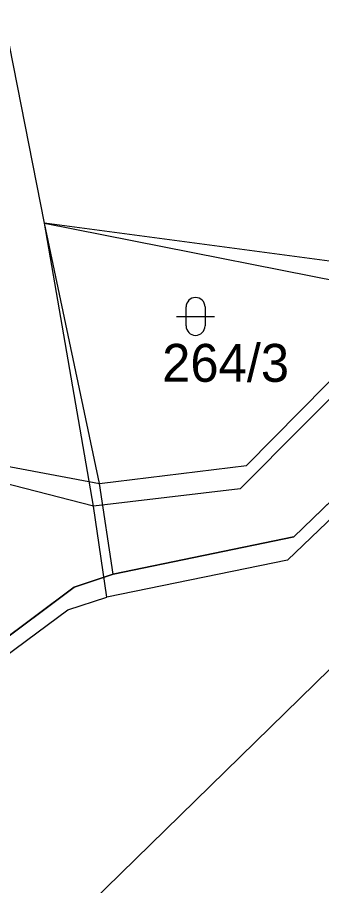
# Model space of a CAD drawing. Extents: x -678683 to -677755, y -1006946 to -1005971.
# Drawn here: x -678311.95 to -678295.9, y -1006533.89 to -1006488.07 of the extents above; entities that cross this region are included whole.
import ezdxf

# ---------------------------------------------------------------- set-up
doc = ezdxf.new("R2010")
doc.units = 0
for name, color, linetype in [('I_2_4_předběžný_vykres - SŽDC', 7, 'Continuous'), ('koor - SSZT_nové', 7, 'Continuous'), ('MapaKN - Mladejov+Strelec_dosavani+nova_situace - Vrstva 1', 7, 'Continuous'), ('MapaKN - Mladejov+Strelec_dosavani+nova_situace - Vrstva 11', 7, 'Continuous'), ('MapaKN - Mladejov+Strelec_dosavani+nova_situace - Vrstva 18', 7, 'Continuous'), ('MapaKN - Mladejov+Strelec_dosavani+nova_situace - Vrstva 25', 7, 'Continuous'), ('MapaKN - původní vrstava 1', 7, 'Continuous')]:
    doc.layers.add(name, color=color, linetype=linetype)

msp = doc.modelspace()

# ---------------------------------------------------------------- linework, layer by layer
at = {"layer": 'I_2_4_předběžný_vykres - SŽDC'}
for p, q in [((-678286.495, -1006504.981), (-678297.37, -1006515.48)), ((-678297.37, -1006515.48), (-678306.89, -1006517.45)), ((-678306.89, -1006517.45), (-678308.95, -1006518.13)), ((-678308.95, -1006518.13), (-678313.38, -1006521.44))]:
    msp.add_line(p, q, dxfattribs=at)
at = {"layer": 'koor - SSZT_nové'}
msp.add_lwpolyline([(-678506.624, -1006791.938), (-678466.12, -1006753.227), (-678449.329, -1006728.75), (-678428.753, -1006695.612), (-678421.07, -1006681.971), (-678401.666, -1006635.236), (-678393.87, -1006623.108), (-678390.132, -1006617.261), (-678380.001, -1006603.755), (-678359.836, -1006584.701), (-678339.66, -1006565.68), (-678276.518, -1006503.932), (-678276.518, -1006503.932)], dxfattribs=at)
at = {"layer": 'MapaKN - Mladejov+Strelec_dosavani+nova_situace - Vrstva 1'}
msp.add_lwpolyline([(-678310.51, -1006498.93), (-678316.86, -1006466.7)], dxfattribs=at)
at = {"layer": 'MapaKN - Mladejov+Strelec_dosavani+nova_situace - Vrstva 11'}
for points in [[(-678289.95, -1006501.68), (-678310.51, -1006498.93)], [(-678307.61, -1006512.66), (-678310.51, -1006498.93)], [(-678299.87, -1006511.71), (-678289.95, -1006501.68)], [(-678297.37, -1006515.48), (-678282.9, -1006501.51)], [(-678326.05, -1006509.2), (-678307.61, -1006512.66)], [(-678307.61, -1006512.66), (-678299.87, -1006511.71)], [(-678306.89, -1006517.45), (-678307.61, -1006512.66)], [(-678306.89, -1006517.45), (-678297.37, -1006515.48)], [(-678308.95, -1006518.13), (-678306.89, -1006517.45)], [(-678313.38, -1006521.44), (-678308.95, -1006518.13)]]:
    msp.add_lwpolyline(points, dxfattribs=at)
at = {"layer": 'MapaKN - Mladejov+Strelec_dosavani+nova_situace - Vrstva 25'}
for points in [[(-678303.05, -1006504.35), (-678303.05, -1006503.35)], [(-678302.05, -1006503.35), (-678302.05, -1006504.35)], [(-678303.55, -1006503.85), (-678301.55, -1006503.85)]]:
    msp.add_lwpolyline(points, dxfattribs=at)
for centre, start, end in [((-678302.55, -1006503.35), 0.101, 180.0014), ((-678302.55, -1006504.35), 180.1024, 0.0029)]:
    msp.add_arc(centre, 0.5, start, end, dxfattribs=at)
at = {"layer": 'MapaKN - původní vrstava 1'}
for points in [[(-678310.51, -1006498.93), (-678290.24, -1006502.94)], [(-678307.93, -1006513.86), (-678310.51, -1006498.93)], [(-678290.24, -1006502.94), (-678300.19, -1006512.94)], [(-678283.19, -1006502.8), (-678297.7, -1006516.72)], [(-678307.93, -1006513.86), (-678326.05, -1006509.2)], [(-678300.19, -1006512.94), (-678307.93, -1006513.86)], [(-678307.23, -1006518.66), (-678307.93, -1006513.86)], [(-678297.7, -1006516.72), (-678307.23, -1006518.66)], [(-678309.29, -1006519.33), (-678307.23, -1006518.66)], [(-678313.73, -1006522.63), (-678309.29, -1006519.33)]]:
    msp.add_lwpolyline(points, dxfattribs=at)

# ---------------------------------------------------------------- texts
at = {"layer": 'MapaKN - Mladejov+Strelec_dosavani+nova_situace - Vrstva 18'}
msp.add_text('264/3', height=2, dxfattribs=at).set_placement((-678304.31, -1006507.3))

doc.saveas('drawing.dxf')
